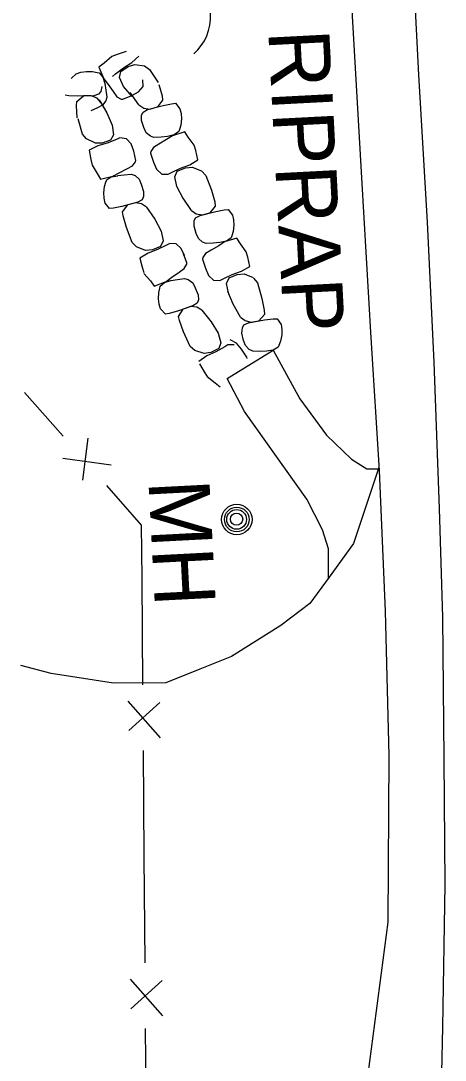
# Model space of a CAD drawing. Extents: x 588843 to 2552415, y 180129 to 269402.
# Drawn here: x 593481.8 to 593523.6, y 186248 to 186350.4 of the extents above; entities that cross this region are included whole.
import ezdxf

# ---------------------------------------------------------------- set-up
doc = ezdxf.new("R2010")
doc.units = 0
for name, color, linetype in [('Default', 7, 'Continuous'), ('E_DRN', 7, 'Continuous'), ('E_DRN_RipRap', 7, 'Continuous'), ('E_DRN_RipRap_Text', 7, 'Continuous'), ('E_DWY', 7, 'Continuous'), ('E_FEN_P', 7, 'Continuous'), ('E_RDWY', 7, 'Continuous'), ('E_RDWY_Gravel', 7, 'Continuous'), ('E_UTL_MH', 7, 'Continuous'), ('E_UTL_MH_Text', 7, 'Continuous')]:
    doc.layers.add(name, color=color, linetype=linetype)

# ---------------------------------------------------------------- blocks, each defined once
blk = doc.blocks.new('CULV2')
at = {"layer": 'E_DRN'}
blk.add_arc((19.68, 14.76), 24.6, 216.8699, 323.1301, dxfattribs=at)
blk = doc.blocks.new('MHO')
at = {"layer": 'Default'}
for centre, radius in [((0.08, -0.12), 3), ((0.08, -0.12), 2.43), ((0.07, -0.15), 1.94), ((0.02, -0.16), 1.21)]:
    blk.add_circle(centre, radius, dxfattribs=at)
blk = doc.blocks.new('MHT')
at = {"layer": 'E_UTL_MH_Text'}
blk.add_text('MH', height=12, dxfattribs=at).set_placement((-9.81, -6))
blk = doc.blocks.new('RIPRT')
at = {"layer": 'E_DRN_RipRap_Text'}
blk.add_text('RIPRAP', height=12, dxfattribs=at).set_placement((-0.14, -3.59))

msp = doc.modelspace()

# ---------------------------------------------------------------- linework, layer by layer
at = {"layer": 'E_DRN_RipRap'}
for p, q in [((593490.76, 186346.84), (593490.01, 186346.21)), ((593491.27, 186347.05), (593490.76, 186346.84)), ((593492.16, 186347.34), (593491.27, 186347.05)), ((593492.72, 186346.25), (593493.41, 186346.9)), ((593487.7, 186345.32), (593488.24, 186345.39)), ((593488.24, 186345.39), (593488.86, 186345.37)), ((593490.01, 186346.21), (593489.48, 186345.8)), ((593489.48, 186345.8), (593489.96, 186344.64)), ((593491.1, 186345.14), (593491.9, 186345.73)), ((593491.65, 186345.37), (593492.36, 186345.87)), ((593491.9, 186345.73), (593492.72, 186346.25)), ((593492.36, 186345.87), (593493.01, 186346.06)), ((593493.01, 186346.06), (593493.96, 186345.92)), ((593493.96, 186345.92), (593494.47, 186345.58)), ((593494.47, 186345.58), (593495.3, 186344.28)), ((593486.74, 186344.68), (593487.24, 186345.16)), ((593487.24, 186345.16), (593487.7, 186345.32)), ((593488.86, 186345.37), (593489.31, 186345.28)), ((593489.31, 186345.28), (593489.49, 186345.23)), ((593489.49, 186345.23), (593489.86, 186344.81)), ((593489.86, 186344.81), (593490.06, 186344.18)), ((593489.96, 186344.64), (593490.38, 186344.1)), ((593490.83, 186344.89), (593491.1, 186345.14)), ((593491.52, 186344.78), (593491.65, 186345.37)), ((593491.91, 186343.91), (593491.52, 186344.78)), ((593493.82, 186343.91), (593493.81, 186344.54)), ((593489.66, 186343.39), (593489.45, 186343.13)), ((593489.78, 186343.9), (593489.66, 186343.39)), ((593490.06, 186344.18), (593490.16, 186343.54)), ((593490.16, 186343.54), (593490.27, 186342.85)), ((593490.38, 186344.1), (593490.89, 186343.4)), ((593490.89, 186343.4), (593491.25, 186342.89)), ((593492.75, 186342.91), (593491.91, 186343.91)), ((593492.71, 186343), (593493.38, 186343.37)), ((593493.38, 186343.37), (593493.82, 186343.91)), ((593495.36, 186344.1), (593495.69, 186342.97)), ((593486.53, 186342.99), (593486.14, 186343.03)), ((593487.37, 186342.94), (593486.53, 186342.99)), ((593487.26, 186342.01), (593487.3, 186342.42)), ((593487.3, 186342.42), (593487.95, 186342.97)), ((593488.97, 186342.99), (593487.37, 186342.94)), ((593488.73, 186342.98), (593487.95, 186342.97)), ((593489.29, 186342.74), (593488.73, 186342.98)), ((593489.45, 186343.13), (593488.97, 186342.99)), ((593489.68, 186342.33), (593489.29, 186342.74)), ((593489.51, 186342.58), (593490.25, 186341.31)), ((593490.16, 186342.48), (593489.84, 186342.05)), ((593490.27, 186342.85), (593490.16, 186342.48)), ((593491.25, 186342.89), (593491.67, 186342.66)), ((593491.67, 186342.66), (593491.82, 186342.66)), ((593491.82, 186342.66), (593492.71, 186343)), ((593493.41, 186342.09), (593492.57, 186343.3)), ((593495.75, 186342.56), (593495.24, 186341.88)), ((593495.69, 186342.97), (593495.75, 186342.56)), ((593487.32, 186340.82), (593487.26, 186342.01)), ((593489.35, 186341.79), (593488.67, 186341.5)), ((593489.84, 186342.05), (593489.35, 186341.79)), ((593490.25, 186341.31), (593490.78, 186340.1)), ((593493.41, 186342.09), (593493.89, 186341.78)), ((593493.68, 186341.07), (593493.82, 186341.37)), ((593493.82, 186341.37), (593494.26, 186341.62)), ((593493.89, 186341.78), (593494.49, 186341.68)), ((593494.26, 186341.62), (593495.8, 186342.04)), ((593494.49, 186341.68), (593495.24, 186341.88)), ((593495.8, 186342.04), (593496.63, 186342.19)), ((593496.63, 186342.19), (593497.02, 186342.24)), ((593497.02, 186342.24), (593497.46, 186341.71)), ((593497.46, 186341.71), (593497.57, 186341.24)), ((593487.86, 186339.21), (593487.42, 186340.71)), ((593493.68, 186340.55), (593493.68, 186341.07)), ((593493.91, 186339.85), (593493.68, 186340.55)), ((593497.61, 186340.71), (593497.53, 186340.09)), ((593497.57, 186341.24), (593497.61, 186340.71)), ((593490.78, 186340.1), (593490.92, 186339.14)), ((593494.13, 186339.35), (593493.91, 186339.85)), ((593494.54, 186339), (593494.13, 186339.35)), ((593497.92, 186339.44), (593496.71, 186339.05)), ((593497.34, 186339.48), (593496.9, 186339.14)), ((593497.4, 186339.65), (593497.34, 186339.48)), ((593497.53, 186340.09), (593497.4, 186339.65)), ((593498.28, 186338.9), (593497.92, 186339.44)), ((593488.26, 186338.73), (593487.86, 186339.21)), ((593489.13, 186338.32), (593488.26, 186338.73)), ((593489.81, 186338.32), (593489.13, 186338.32)), ((593490.29, 186338.32), (593489.36, 186338.05)), ((593490.63, 186338.6), (593489.81, 186338.32)), ((593491.22, 186338.68), (593490.29, 186338.32)), ((593490.92, 186339.14), (593490.63, 186338.6)), ((593491.55, 186338.84), (593491.22, 186338.68)), ((593492.18, 186338.76), (593491.55, 186338.84)), ((593492.65, 186338.25), (593492.18, 186338.76)), ((593492.91, 186337.54), (593492.65, 186338.25)), ((593494.9, 186338.87), (593494.54, 186339)), ((593495.6, 186338.92), (593494.9, 186338.87)), ((593496.13, 186338.67), (593495.39, 186338.22)), ((593496.24, 186338.99), (593495.6, 186338.92)), ((593496.71, 186339.05), (593496.13, 186338.67)), ((593496.9, 186339.14), (593496.24, 186338.99)), ((593498.85, 186338.11), (593498.28, 186338.9)), ((593489.36, 186338.05), (593488.52, 186337.62)), ((593488.52, 186337.62), (593488.67, 186336.7)), ((593493.12, 186336.62), (593492.91, 186337.54)), ((593494.59, 186337.49), (593494.57, 186337.34)), ((593494.57, 186337.34), (593494.85, 186336.44)), ((593494.86, 186337.89), (593494.59, 186337.49)), ((593495.39, 186338.22), (593494.86, 186337.89)), ((593499.02, 186337.59), (593498.85, 186338.11)), ((593499.23, 186336.69), (593499.02, 186337.59)), ((593488.67, 186336.7), (593488.8, 186336.16)), ((593492.8, 186336.09), (593493.09, 186336.47)), ((593493.09, 186336.47), (593493.12, 186336.62)), ((593494.85, 186336.44), (593495.16, 186335.75)), ((593497.51, 186335.85), (593498.42, 186336.19)), ((593498.42, 186336.19), (593499.23, 186336.69)), ((593488.8, 186336.16), (593489.31, 186335.33)), ((593489.31, 186335.33), (593489.63, 186334.76)), ((593490.86, 186335.07), (593491.46, 186335.4)), ((593491.32, 186335.14), (593491.96, 186335.2)), ((593491.46, 186335.4), (593492.24, 186335.8)), ((593491.96, 186335.2), (593492.66, 186335.26)), ((593492.24, 186335.8), (593492.8, 186336.09)), ((593492.66, 186335.26), (593493.03, 186335.12)), ((593495.16, 186335.75), (593495.66, 186335.28)), ((593495.66, 186335.28), (593496.29, 186335.25)), ((593496.29, 186335.25), (593496.61, 186335.43)), ((593496.61, 186335.43), (593497.51, 186335.85)), ((593496.95, 186334.99), (593497.19, 186335.55)), ((593497.19, 186335.55), (593497.99, 186335.89)), ((593497.99, 186335.89), (593498.67, 186335.94)), ((593498.67, 186335.94), (593499.57, 186335.6)), ((593499.57, 186335.6), (593500, 186335.15)), ((593489.63, 186334.76), (593490.86, 186335.07)), ((593490.03, 186334.04), (593490.16, 186334.48)), ((593490.16, 186334.48), (593490.22, 186334.65)), ((593490.2, 186334.69), (593490.67, 186334.99)), ((593490.67, 186334.99), (593491.34, 186335.1)), ((593493.03, 186335.12), (593493.43, 186334.77)), ((593493.43, 186334.77), (593493.65, 186334.27)), ((593493.65, 186334.27), (593493.88, 186333.57)), ((593497.15, 186334.05), (593496.95, 186334.99)), ((593500, 186335.15), (593500.55, 186333.69)), ((593489.95, 186333.42), (593490.03, 186334.04)), ((593489.98, 186332.89), (593489.95, 186333.42)), ((593493.88, 186333.57), (593493.88, 186333.05)), ((593497.76, 186332.88), (593497.15, 186334.05)), ((593500.56, 186333.68), (593500.88, 186332.54)), ((593490.1, 186332.42), (593489.98, 186332.89)), ((593490.53, 186331.89), (593490.1, 186332.42)), ((593491.75, 186332.08), (593490.92, 186331.93)), ((593493.3, 186332.5), (593491.75, 186332.08)), ((593491.81, 186331.56), (593492.31, 186332.25)), ((593493.07, 186332.44), (593492.31, 186332.25)), ((593493.67, 186332.34), (593493.07, 186332.44)), ((593493.74, 186332.75), (593493.3, 186332.5)), ((593494.15, 186332.02), (593493.67, 186332.34)), ((593493.88, 186333.05), (593493.74, 186332.75)), ((593498.58, 186331.69), (593497.76, 186332.91)), ((593500.93, 186332.13), (593500.41, 186331.45)), ((593500.88, 186332.54), (593500.93, 186332.13)), ((593490.92, 186331.93), (593490.53, 186331.89)), ((593491.86, 186331.15), (593491.81, 186331.56)), ((593492.19, 186330.01), (593491.86, 186331.15)), ((593494.15, 186332.02), (593494.98, 186330.82)), ((593498.58, 186331.69), (593499.06, 186331.37)), ((593498.99, 186330.96), (593499.43, 186331.2)), ((593499.06, 186331.37), (593499.66, 186331.26)), ((593499.43, 186331.2), (593500.98, 186331.6)), ((593499.66, 186331.26), (593500.41, 186331.45)), ((593500.98, 186331.6), (593501.81, 186331.74)), ((593501.81, 186331.74), (593502.2, 186331.79)), ((593502.2, 186331.79), (593502.63, 186331.24)), ((593502.63, 186331.24), (593502.74, 186330.77)), ((593494.98, 186330.82), (593495.59, 186329.64)), ((593498.84, 186330.66), (593498.99, 186330.96)), ((593498.84, 186330.14), (593498.84, 186330.66)), ((593499.06, 186329.43), (593498.84, 186330.14)), ((593502.77, 186330.24), (593502.69, 186329.62)), ((593502.74, 186330.77), (593502.77, 186330.24)), ((593492.74, 186328.55), (593492.19, 186330.01)), ((593495.59, 186329.64), (593495.8, 186328.7)), ((593499.27, 186328.93), (593499.06, 186329.43)), ((593502.55, 186329.18), (593502.49, 186329.01)), ((593502.69, 186329.62), (593502.55, 186329.18)), ((593493.17, 186328.1), (593492.74, 186328.55)), ((593494.07, 186327.76), (593493.17, 186328.1)), ((593495.55, 186328.14), (593494.75, 186327.8)), ((593496.13, 186328.26), (593495.23, 186327.84)), ((593495.8, 186328.7), (593495.55, 186328.14)), ((593496.45, 186328.45), (593496.13, 186328.26)), ((593497.08, 186328.41), (593496.45, 186328.45)), ((593497.58, 186327.93), (593497.08, 186328.41)), ((593499.67, 186328.58), (593499.27, 186328.93)), ((593500.04, 186328.43), (593499.67, 186328.58)), ((593500.74, 186328.48), (593500.04, 186328.43)), ((593501.27, 186328.22), (593500.52, 186327.77)), ((593501.38, 186328.53), (593500.74, 186328.48)), ((593501.85, 186328.59), (593501.27, 186328.22)), ((593502.04, 186328.68), (593501.38, 186328.53)), ((593503.06, 186328.97), (593501.85, 186328.59)), ((593502.49, 186329.01), (593502.04, 186328.68)), ((593503.42, 186328.41), (593503.06, 186328.97)), ((593503.98, 186327.61), (593503.42, 186328.41)), ((593494.32, 186327.5), (593493.51, 186327.01)), ((593493.51, 186327.01), (593493.72, 186326.11)), ((593494.75, 186327.8), (593494.07, 186327.76)), ((593495.23, 186327.84), (593494.32, 186327.5)), ((593497.89, 186327.25), (593497.58, 186327.93)), ((593498.13, 186326.55), (593497.79, 186327.43)), ((593499.71, 186327.06), (593499.69, 186326.91)), ((593499.98, 186327.45), (593499.71, 186327.06)), ((593500.52, 186327.77), (593499.98, 186327.45)), ((593504.14, 186327.09), (593503.98, 186327.61)), ((593504.35, 186326.18), (593504.14, 186327.09)), ((593493.72, 186326.11), (593493.89, 186325.59)), ((593497.37, 186325.62), (593497.88, 186325.98)), ((593497.88, 186325.98), (593498.12, 186326.39)), ((593498.12, 186326.39), (593498.13, 186326.55)), ((593499.69, 186326.91), (593499.96, 186326)), ((593499.96, 186326), (593500.26, 186325.3)), ((593503.53, 186325.7), (593504.35, 186326.18)), ((593493.91, 186325.5), (593494.54, 186324.75)), ((593496.11, 186324.7), (593496.66, 186325.11)), ((593496.66, 186325.11), (593497.37, 186325.62)), ((593497.21, 186324.9), (593497.91, 186325)), ((593497.91, 186325), (593498.28, 186324.89)), ((593500.26, 186325.3), (593500.76, 186324.82)), ((593501.39, 186324.78), (593501.71, 186324.96)), ((593501.71, 186324.96), (593502.61, 186325.37)), ((593502.04, 186324.51), (593502.29, 186325.07)), ((593502.29, 186325.07), (593503.09, 186325.4)), ((593502.61, 186325.37), (593503.53, 186325.7)), ((593503.09, 186325.4), (593503.77, 186325.44)), ((593503.77, 186325.44), (593504.67, 186325.09)), ((593504.7, 186325.04), (593505.09, 186324.55)), ((593494.54, 186324.75), (593494.93, 186324.23)), ((593494.93, 186324.23), (593496.11, 186324.7)), ((593495.36, 186323.6), (593495.46, 186324.05)), ((593495.46, 186324.05), (593495.51, 186324.23)), ((593495.51, 186324.23), (593495.93, 186324.6)), ((593495.93, 186324.6), (593496.57, 186324.79)), ((593496.57, 186324.79), (593497.21, 186324.9)), ((593498.28, 186324.89), (593498.71, 186324.57)), ((593498.71, 186324.57), (593498.96, 186324.08)), ((593498.96, 186324.08), (593499.24, 186323.4)), ((593500.76, 186324.82), (593501.39, 186324.78)), ((593502.23, 186323.57), (593502.04, 186324.51)), ((593505.09, 186324.55), (593505.52, 186323.03)), ((593495.33, 186322.98), (593495.36, 186323.6)), ((593495.4, 186322.45), (593495.33, 186322.98)), ((593499.27, 186322.88), (593499.15, 186322.57)), ((593499.24, 186323.4), (593499.27, 186322.88)), ((593502.68, 186322.47), (593502.16, 186323.7)), ((593505.52, 186323.03), (593505.76, 186321.87)), ((593495.54, 186321.99), (593495.4, 186322.45)), ((593496.02, 186321.49), (593495.54, 186321.99)), ((593498.74, 186322.29), (593497.22, 186321.77)), ((593497.31, 186321.25), (593497.77, 186321.97)), ((593498.51, 186322.22), (593497.77, 186321.97)), ((593499.12, 186322.16), (593498.51, 186322.22)), ((593499.15, 186322.57), (593498.74, 186322.29)), ((593499.62, 186321.88), (593499.12, 186322.16)), ((593499.62, 186321.88), (593500.53, 186320.73)), ((593503.41, 186321.19), (593502.68, 186322.47)), ((593505.76, 186321.87), (593505.78, 186321.46)), ((593496.4, 186321.56), (593496.02, 186321.49)), ((593497.22, 186321.77), (593496.4, 186321.56)), ((593497.4, 186320.85), (593497.31, 186321.25)), ((593497.81, 186319.74), (593497.4, 186320.85)), ((593503.41, 186321.19), (593503.86, 186320.84)), ((593503.86, 186320.84), (593504.45, 186320.68)), ((593504.22, 186320.64), (593505.79, 186320.92)), ((593505.78, 186321.46), (593505.22, 186320.81)), ((593505.79, 186320.92), (593506.64, 186321.01)), ((593506.64, 186321.01), (593507.02, 186321.02)), ((593507.02, 186321.02), (593507.42, 186320.45)), ((593500.53, 186320.73), (593501.23, 186319.6)), ((593503.55, 186319.62), (593503.6, 186320.14)), ((593503.6, 186320.14), (593503.76, 186320.43)), ((593503.76, 186320.43), (593504.22, 186320.64)), ((593504.45, 186320.68), (593505.22, 186320.81)), ((593507.42, 186320.45), (593507.49, 186319.97)), ((593507.49, 186319.97), (593507.48, 186319.43)), ((593498.46, 186318.31), (593497.81, 186319.74)), ((593501.23, 186319.6), (593501.49, 186318.67)), ((593503.03, 186318.62), (593502.41, 186318.94)), ((593503.72, 186318.9), (593503.55, 186319.62)), ((593503.9, 186318.38), (593503.72, 186318.9)), ((593507.36, 186318.82), (593507.19, 186318.39)), ((593507.48, 186319.43), (593507.36, 186318.82)), ((593498.92, 186317.89), (593498.46, 186318.31)), ((593499.84, 186317.61), (593498.92, 186317.89)), ((593500.99, 186317.77), (593500.1, 186317.37)), ((593501.29, 186318.1), (593500.51, 186317.7)), ((593501.86, 186318.25), (593500.99, 186317.77)), ((593501.49, 186318.67), (593501.29, 186318.1)), ((593502.16, 186318.46), (593501.86, 186318.25)), ((593502.8, 186318.47), (593502.16, 186318.46)), ((593503.53, 186318.05), (593503.03, 186318.62)), ((593504.05, 186317.26), (593503.53, 186318.05)), ((593504.28, 186318), (593503.9, 186318.38)), ((593504.63, 186317.83), (593504.28, 186318)), ((593505.33, 186317.82), (593504.63, 186317.83)), ((593505.98, 186317.83), (593505.33, 186317.82)), ((593506.64, 186317.92), (593505.98, 186317.83)), ((593507.11, 186318.22), (593506.64, 186317.92)), ((593507.19, 186318.39), (593507.11, 186318.22)), ((593500.1, 186317.37), (593499.33, 186316.83)), ((593500.51, 186317.7), (593499.84, 186317.61)), ((593504.08, 186317.11), (593504.05, 186317.26)), ((593499.37, 186316.6), (593499.84, 186315.79)), ((593499.84, 186315.79), (593500.15, 186315.33)), ((593500.15, 186315.33), (593500.93, 186314.73)), ((593500.93, 186314.73), (593501.43, 186314.31))]:
    msp.add_line(p, q, dxfattribs=at)
at = {"layer": 'E_DWY'}
msp.add_lwpolyline([(593517.05, 186306.38), (593514.54, 186298.89), (593512.16, 186295.57), (593510.25, 186292.98), (593507.4, 186290.81), (593502.53, 186287.77), (593499.42, 186286.52), (593496.07, 186285.17), (593490.9, 186285.16), (593484.77, 186286.09), (593481.79, 186286.87)], dxfattribs=at)
at = {"layer": 'E_FEN_P'}
for p, q in [((593488.4, 186309.26), (593487.87, 186305.15)), ((593485.91, 186307.29), (593490.69, 186306.64)), ((593492.32, 186283.37), (593495.52, 186279.76)), ((593495.49, 186283.23), (593492.41, 186280.47)), ((593492.54, 186256), (593495.74, 186252.38)), ((593495.71, 186255.86), (593492.62, 186253.09))]:
    msp.add_line(p, q, dxfattribs=at)
for points in [[(593482.16, 186313.78), (593485.95, 186309.46)], [(593490.21, 186304.6), (593493.65, 186300.69), (593493.69, 186295.44)], [(593493.69, 186295.44), (593493.77, 186284.99)], [(593493.82, 186278.52), (593493.9, 186268.07)], [(593493.9, 186268.07), (593493.99, 186257.62)], [(593494.04, 186251.15), (593494.06, 186248), (593494, 186240.7)]]:
    msp.add_lwpolyline(points, dxfattribs=at)
at = {"layer": 'E_RDWY'}
for points in [[(593522.19, 186222.82), (593522.62, 186231.68), (593523.15, 186242.3), (593523.35, 186251.28), (593523.57, 186265.33), (593523.48, 186277.68), (593523.35, 186291.64), (593523.02, 186302.33), (593522.47, 186316.77), (593521.83, 186330.55), (593520.97, 186345.05), (593520.15, 186361.14)], [(593512.08, 186295.46), (593512.08, 186298.37), (593511.49, 186300.24), (593509.96, 186303.25), (593503.8, 186311.9), (593502.09, 186315.13), (593506.64, 186317.92), (593509.25, 186313.15), (593511.89, 186309.58), (593514.36, 186307.21), (593515.85, 186306.26), (593517, 186306.25)]]:
    msp.add_lwpolyline(points, dxfattribs=at)
at = {"layer": 'E_RDWY_Gravel'}
msp.add_lwpolyline([(593502.85, 186516.74), (593507.2, 186487.8), (593508.02, 186471.3), (593509.21, 186451.45), (593509.99, 186435.54), (593511.04, 186417.49), (593511.84, 186402.54), (593512.47, 186387.31), (593513.25, 186371.5), (593514.09, 186356.57), (593515.33, 186334.92), (593516.26, 186319.15), (593517.07, 186306.1), (593517.66, 186292.24), (593518.01, 186278.03), (593517.91, 186261.6), (593514.79, 186237.91)], dxfattribs=at)

# ---------------------------------------------------------------- block references
at = {"layer": 'E_DRN', "xscale": 0.19389007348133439, "yscale": 0.19389007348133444, "rotation": 93.93107579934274}
msp.add_blockref('CULV2', (593498.81, 186347.12), dxfattribs=at)
at = {"layer": 'E_DRN_RipRap_Text', "xscale": 0.5000000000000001, "yscale": 0.5, "rotation": -87.02058409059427}
msp.add_blockref('RIPRT', (593507.94, 186349.39), dxfattribs=at)
at = {"layer": 'E_UTL_MH', "xscale": 0.5000000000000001, "yscale": 0.5, "rotation": -87.02058409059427}
msp.add_blockref('MHO', (593503.11, 186301.31), dxfattribs=at)
at = {"layer": 'E_UTL_MH_Text', "xscale": 0.5000000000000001, "yscale": 0.5, "rotation": -87.02058409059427}
msp.add_blockref('MHT', (593497.6, 186300.31), dxfattribs=at)

doc.saveas('drawing.dxf')
